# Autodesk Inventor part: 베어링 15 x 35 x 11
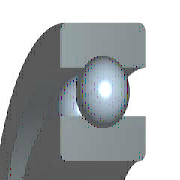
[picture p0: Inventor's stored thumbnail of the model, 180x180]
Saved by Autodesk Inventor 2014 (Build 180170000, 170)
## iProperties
Created: 2012-02
Part Number: 베어링 15 x 35 x 11
Material: 강철, 연강
Description: 깊은 그루브 볼 베어링
Document SubType Name: Modeling
Standard: KS B 2023
Designer: mduedu
Standards Organization: KS
Language: ko-KR
Size Designation: 6202 - 15 x 35 x 11
Categories: <MemberInstance><Categories><Category DisplayName="샤프트 부품" InternalName="7f7aeb1f-a693-4053-b835-cee3144e0d98" Mnemonic="SHFT"><Category DisplayName="베어링" Inter
Density: 1 g/cm^3
Appearance: 노란색
IsCustomPart: 1
Author: mduedu
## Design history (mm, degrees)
sketch "스케치" dims "d0" = 5.2 (= -0.26 x WD + 0.26 x BD)
  geometry: L1 (2.9, 12.5)-(8.1, 12.5); L2 (5.5, 12.5)-(5.5, 9.9); L3 (5.5, 12.5)-(5.5, 15.1); L4 (3.568, 10.76)-(0, 10.76); L5 (0, 7.5)-(11, 7.5); L6 (3.568, 14.24)-(0, 14.24); L7 (0, 17.5)-(11, 17.5); L8 (11, 7.5)-(11, 10.76); L9 (7.432, 10.76)-(11, 10.76); L10 (7.432, 14.24)-(11, 14.24); L11 (11, 17.5)-(11, 14.24); L12 (-1.4, 0)-(8.4, 0) reference; L13 (0, -0.3)-(0, 5.3) reference
  constraints: 22 end point, 4 point on line, 2 collinear, 2 perpendicular, 2 symmetric about line, 1 midpoint, 1 parallel, 14 other
  dimensions: "d9" = 15 diameter of L5 L12 (= WD); "d11" = 35 diameter of L7 L12 (= BD); "d12" = 11 distance between parallel lines of L8 L13 (= KB); "d13" = 21.52 diameter of L9 L12 (= 0.326 x BD + 0.674 x WD)
revolve "본체" stored, may be unused: angle "d6" = 90 deg
revolve "볼" stored, may be unused: angle "d7" = 90 deg
pattern_circular "IDS_ARRAYBALL[SIMPL:T]" dims angle "d3" = 360 deg
body "Solid1"
fillet "모깎기1" dims "d1" = 0.6 (= KRS)
other parameters: "WD" = 15 [user parameter; used in 5 equation terms], "BD" = 35 [user parameter; used in 5 equation terms], "KB" = 11 [user parameter; used in 1 equation term], "KRS" = 0.6 [user parameter; used in 1 equation term], "d4" = 0, "d5" = 0, "d8" = 0, "d14" = 0, "d15" = 0, "BBA" = 0 [user parameter], "BC0" = 3750000 [user parameter], "BC" = 7800000 [user parameter], "BR" = 17.5 (= 0.5 x BD) [user parameter], "WR" = 7.5 (= 0.5 x WD) [user parameter]
